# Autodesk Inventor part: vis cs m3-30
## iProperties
Author: chr
Created: 2002-03
Part Number: vis cs m3-30
Material: Par défaut
Document SubType Name: Modélisation
Designer: chr
Control State: 0
Master: False
Checked Out: False
PropertySet Name: Design Tracking Control
Shininess: 20.0
Angle Display Precision: 2
Document Length Units: 11269
Document Angle Units: 11283
Document Time Units: 11279
Document Mass Units: 11290
Document Length Units Precision: 3
Document Angle Units Precision: 2
Compacted: False
PropertySet Name: _Private Model Information
Density: 0.0
Volumn: 0.0
Area: 0.0
PropertySet Name: Model Information
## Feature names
1. Base1
